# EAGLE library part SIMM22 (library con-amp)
AMP connector
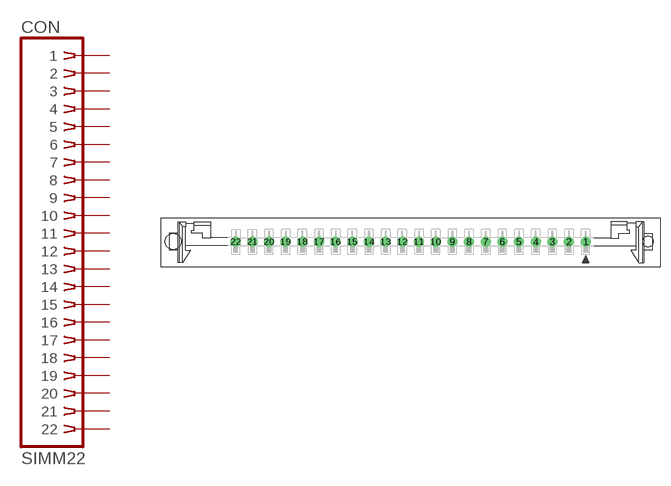
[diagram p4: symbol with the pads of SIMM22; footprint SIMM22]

Designator prefix CON

## SIMM22 (OC_FARNELL: unknown; OC_NEWARK: unknown)  [SIMM22]
1  1  pas
2  2  pas
3  3  pas
4  4  pas
5  5  pas
6  6  pas
7  7  pas
8  8  pas
9  9  pas
10  10  pas
11  11  pas
12  12  pas
13  13  pas
14  14  pas
15  15  pas
16  16  pas
17  17  pas
18  18  pas
19  19  pas
20  20  pas
21  21  pas
22  22  pas

## Footprint SIMM22 (pad centres in mm)
SIMM connector
drill 1.016 round: 1 26.67,0; 2 24.13,0; 3 21.59,0; 4 19.05,0; 5 16.51,0; 6 13.97,0; 7 11.43,0; 8 8.89,0; 9 6.35,0; 10 3.81,0; 11 1.27,0; 12 -1.27,0; 13 -3.81,0; 14 -6.35,0; 15 -8.89,0; 16 -11.43,0; 17 -13.97,0; 18 -16.51,0; 19 -19.05,0; 20 -21.59,0; 21 -24.13,0; 22 -26.67,0
hole 2.413 at -36.22,0.025
hole 1.6 at 36.195,0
